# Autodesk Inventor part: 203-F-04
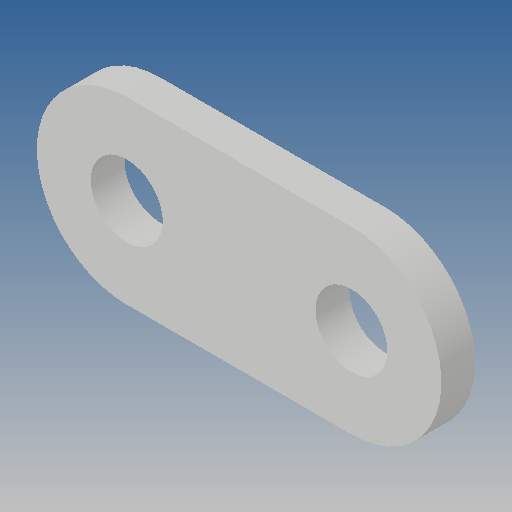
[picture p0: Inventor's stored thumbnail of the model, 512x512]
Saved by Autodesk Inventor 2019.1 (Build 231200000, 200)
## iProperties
Created: 2015-08
Part Number: 203-F-04
Material: Ogólny
Document SubType Name: Modeling
Designer: CADENGINEERING4
Density: 1 g/cm^3
Appearance: Domyślna
Author: CADENGINEERING4
Revision Number: ÈÎºÎ
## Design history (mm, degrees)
feature "À­Éì1"
node "Bryła1"
